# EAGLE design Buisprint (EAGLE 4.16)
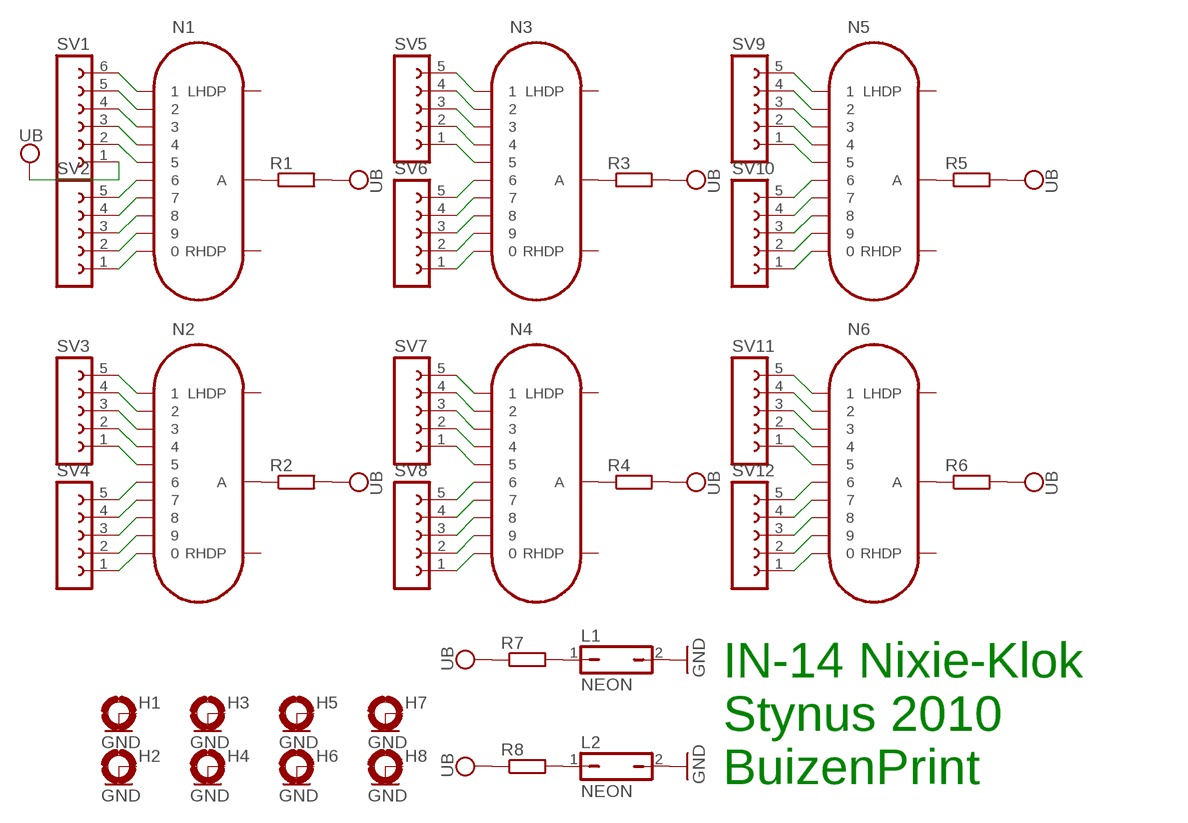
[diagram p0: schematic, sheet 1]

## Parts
H1  MOUNT-PAD-ROUND3.0  [3,0-PAD]
H2  MOUNT-PAD-ROUND3.0  [3,0-PAD]
H3  MOUNT-PAD-ROUND3.0  [3,0-PAD]
H4  MOUNT-PAD-ROUND3.0  [3,0-PAD]
H5  MOUNT-PAD-ROUND3.0  [3,0-PAD]
H6  MOUNT-PAD-ROUND3.0  [3,0-PAD]
H7  MOUNT-PAD-ROUND3.0  [3,0-PAD]
H8  MOUNT-PAD-ROUND3.0  [3,0-PAD]
L1  NEON  JP1Q  [JP1]
L2  NEON  JP1Q  [JP1]
N1  IN-14  [IN-14]
N2  IN-14  [IN-14]
N3  IN-14  [IN-14]
N4  IN-14  [IN-14]
N5  IN-14  [IN-14]
N6  IN-14  [IN-14]
R1  R-EU_0207/10  [0207/10]
R2  R-EU_0207/10  [0207/10]
R3  R-EU_0207/10  [0207/10]
R4  R-EU_0207/10  [0207/10]
R5  R-EU_0207/10  [0207/10]
R6  R-EU_0207/10  [0207/10]
R7  R-EU_0207/10  [0207/10]
R8  R-EU_0207/10  [0207/10]
SV1  FE06-1  [FE06]
SV2  FE05-1  [FE05-1]
SV3  FE05-1  [FE05-1]
SV4  FE05-1  [FE05-1]
SV5  FE05-1  [FE05-1]
SV6  FE05-1  [FE05-1]
SV7  FE05-1  [FE05-1]
SV8  FE05-1  [FE05-1]
SV9  FE05-1  [FE05-1]
SV10  FE05-1  [FE05-1]
SV11  FE05-1  [FE05-1]
SV12  FE05-1  [FE05-1]

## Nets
GND: H1.B3,0(MOUNT) H2.B3,0(MOUNT) H3.B3,0(MOUNT) H4.B3,0(MOUNT) H5.B3,0(MOUNT) H6.B3,0(MOUNT) H7.B3,0(MOUNT) H8.B3,0(MOUNT) L1.2 L2.2
N$1: N1.5 SV1.2
N$2: N1.4 SV1.3
N$3: N1.3 SV1.4
N$4: N1.2 SV1.5
N$5: N1.1 SV1.6
N$6: N1.0 SV2.1
N$7: N1.9 SV2.2
N$8: N1.8 SV2.3
N$9: N1.7 SV2.4
N$10: N1.6 SV2.5
N$11: N2.5 SV3.1
N$12: N2.4 SV3.2
N$13: N2.3 SV3.3
N$14: N2.2 SV3.4
N$15: N2.1 SV3.5
N$16: N2.0 SV4.1
N$17: N2.9 SV4.2
N$18: N2.8 SV4.3
N$19: N2.7 SV4.4
N$20: N2.6 SV4.5
N$21: N3.5 SV5.1
N$22: N3.4 SV5.2
N$23: N3.3 SV5.3
N$24: N3.2 SV5.4
N$25: N3.1 SV5.5
N$26: N3.0 SV6.1
N$27: N3.9 SV6.2
N$28: N3.8 SV6.3
N$29: N3.7 SV6.4
N$30: N3.6 SV6.5
N$31: N4.5 SV7.1
N$32: N4.4 SV7.2
N$33: N4.3 SV7.3
N$34: N4.2 SV7.4
N$35: N4.1 SV7.5
N$36: N4.0 SV8.1
N$37: N4.9 SV8.2
N$38: N4.8 SV8.3
N$39: N4.7 SV8.4
N$40: N4.6 SV8.5
N$41: N5.5 SV9.1
N$42: N5.4 SV9.2
N$43: N5.3 SV9.3
N$44: N5.2 SV9.4
N$45: N5.1 SV9.5
N$46: N5.0 SV10.1
N$47: N5.9 SV10.2
N$48: N5.8 SV10.3
N$49: N5.7 SV10.4
N$50: N5.6 SV10.5
N$51: N6.5 SV11.1
N$52: N6.4 SV11.2
N$53: N6.3 SV11.3
N$54: N6.2 SV11.4
N$55: N6.1 SV11.5
N$56: N6.0 SV12.1
N$57: N6.9 SV12.2
N$58: N6.8 SV12.3
N$59: N6.7 SV12.4
N$60: N6.6 SV12.5
N$61: N1.A R1.1
N$62: N2.A R2.1
N$63: N3.A R3.1
N$64: N4.A R4.1
N$65: N5.A R5.1
N$66: N6.A R6.1
N$67: L1.1 R7.2
N$68: L2.1 R8.2
VSS: R1.2 R2.2 R3.2 R4.2 R5.2 R6.2 R7.1 R8.1 SV1.1 ; supply symbol labelled UB
Unconnected: N1.LHDP N1.RHDP N2.LHDP N2.RHDP N3.LHDP N3.RHDP N4.LHDP N4.RHDP N5.LHDP N5.RHDP N6.LHDP N6.RHDP

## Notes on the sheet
- IN-14 Nixie-Klok
- Stynus 2010
- BuizenPrint

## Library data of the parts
H1-H8 = holes:MOUNT-PAD-ROUND: MOUNTING PAD, round
L1 L2 = jumper:JP1Q: JUMPER
N1-N6 = russian-nixies:IN-14: IN-14: medium numeric frontview nixie tube
R1-R8 = rcl:R-EU_: RESISTOR, European symbol
SV1 = con-lsta:FE06-1: FEMALE HEADER
SV2-SV12 = con-lsta:FE05-1: FEMALE HEADER

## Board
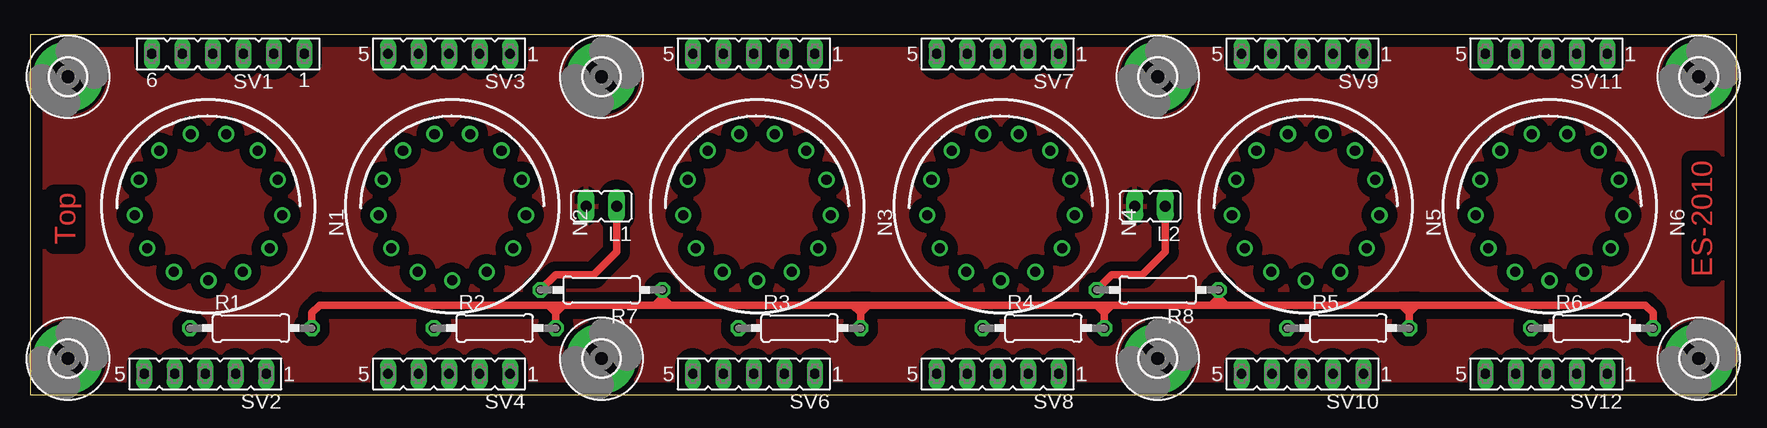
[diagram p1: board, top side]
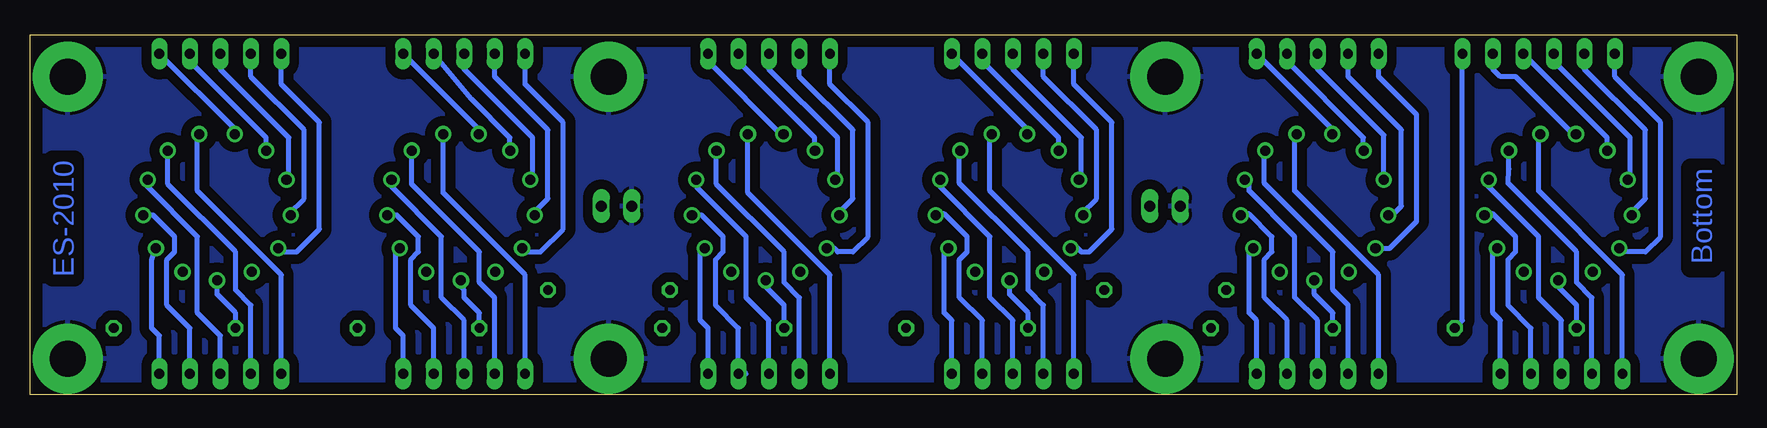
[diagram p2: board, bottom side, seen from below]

Size 142.22 x 30 mm. Coordinates in mm from the lower left corner, seen from the top.
Outline: 0,0 142.22,0 142.22,30 0,30 0,0
Copper layers (1*16): Top 0.035mm / dielectric 1.5mm / Bottom 0.035mm
Design rules "default": minimum track width 10mil, minimum drill 24mil, track to track 8mil, track to pad 8mil, pad to pad 8mil, via to via 8mil, smd to smd 8mil, copper to edge 40mil, drill to drill 8mil, minimum pad ring 10mil, minimum via ring 8mil, stop-mask expansion 4mil, vias tented up to drill 0mil, thermal gap 10mil

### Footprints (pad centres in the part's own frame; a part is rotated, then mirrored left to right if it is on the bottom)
3,0-PAD = drill 3 pad 5.842 round: B3,0 0,0
JP1 = drill 0.914 long: 1 0,-1.27; 2 0,1.27
IN-14 = drill 0.84 round: 0 5.094,-3.516; 1 -5.094,-3.516; 2 -6.145,-0.746; 3 -5.788,2.195; 4 -4.105,4.633; 5 -1.481,6.01; 6 1.481,6.01; 7 4.105,4.633; 8 5.788,2.195; 9 6.145,-0.746; A 0,-6.19; LHDP 2.877,-5.481; RHDP -2.877,-5.481
0207/10 = drill 0.813 octagon: 1 -5.08,0; 2 5.08,0
FE06 = drill 0.813 long: 1 -6.35,0; 2 -3.81,0; 3 -1.27,0; 4 1.27,0; 5 3.81,0; 6 6.35,0
FE05-1 = drill 0.813 long: 1 -5.08,0; 2 -2.54,0; 3 0,0; 4 2.54,0; 5 5.08,0

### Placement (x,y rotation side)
H1  3.17,26.5 0 top
H2  3.17,3.01 0 top
H3  47.62,26.5 0 top
H4  47.62,3.01 0 top
H5  93.97,26.5 0 top
H6  93.97,3.01 0 top
H7  139.06,26.5 0 top
H8  139.06,3.01 0 top
L1  47.62,15.71 90 top
L2  93.34,15.71 90 top
N1  14.87,15.71 0 top
N2  35.19,15.71 0 top
N3  60.59,15.71 0 top
N4  80.91,15.71 0 top
N5  106.31,15.71 0 top
N6  126.63,15.71 0 top
R1  18.41,5.55 0 top
R2  38.73,5.55 0 top
R3  64.13,5.55 0 top
R4  84.45,5.55 0 top
R5  109.85,5.55 0 top
R6  130.17,5.55 0 top
R7  47.62,8.73 180 top
R8  93.97,8.73 180 top
SV1  16.5,28.41 180 top
SV2  14.6,1.74 180 top
SV3  34.92,28.41 180 top
SV4  34.92,1.74 180 top
SV5  60.32,28.41 180 top
SV6  60.32,1.74 180 top
SV7  80.64,28.41 180 top
SV8  80.64,1.74 180 top
SV9  106.04,28.41 180 top
SV10  106.04,1.74 180 top
SV11  126.36,28.41 180 top
SV12  126.36,1.74 180 top

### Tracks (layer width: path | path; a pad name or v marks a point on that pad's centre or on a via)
GND
  pour Bottom (isolate 0.813): -0.01,30.31 142.23,30.31 142.23,-0.17 -0.01,-0.17
  pour Top (isolate 0.813): -0.01,30.31 142.23,30.31 142.23,-0.17 -0.01,-0.17
N$1
  Bottom 0.406: 13.33,22.06 13.39,22 N1.5 13.62,21.72 18.41,26.5 19.68,26.5 20.31,27.14 SV1.2
N$2
  Bottom 0.406: N1.4 10.77,20.77 10.79,20.79 10.79,21.42 SV1.3
N$3
  Bottom 0.406: 8.89,18.25 8.89,21.42 15.24,27.77 SV1.4 | 8.89,18.25 9.08,18.05 N1.3 | 8.89,18.25 9.52,17.61
N$4
  Bottom 0.406: N1.2 8.77,14.96 8.89,15.08 7.62,16.34 7.62,22.06 12.7,27.14 SV1.5
N$5
  Bottom 0.406: N1.1 9.78,12.16 9.52,11.9 7.62,11.9 6.34,13.17 6.34,22.7 10.16,26.5 SV1.6
N$6
  Bottom 0.406: SV2.1 19.68,6.18 20.31,6.82 20.31,11.9 19.97,12.19 N1.0
N$7
  Bottom 0.406: SV2.2 17.14,5.55 19.04,7.46 19.04,11.27 18.41,11.9 18.41,13.17 20.31,15.08 20.95,15.08 21.02,15.01 N1.9
N$8
  Bottom 0.406: SV2.3 14.6,6.18 16.5,8.09 16.5,13.17 20.95,17.61 20.66,17.96 | 20.66,17.96 20.95,18.25 | 20.66,17.96 N1.8
N$9
  Bottom 0.406: N1.7 18.97,18.81 19.04,17.61 13.33,11.9 13.33,9.36 12.06,8.09 SV2.4
N$10
  Bottom 0.406: SV2.5 9.52,10 16.5,16.98 16.5,22.06 16.35,21.91 N1.6
N$11
  Bottom 0.406: N2.5 33.71,22.12 SV3.1
N$12
  Bottom 0.406: SV3.2 37.46,27.77 31.11,21.42 31.11,20.15 31.08,20.18 N2.4
N$13
  Bottom 0.406: N2.3 29.4,21.62 34.92,27.14 SV3.3
N$14
  Bottom 0.406: SV3.4 32.38,26.5 27.93,22.06 27.93,15.71 28.68,14.96 N2.2
N$15
  Bottom 0.406: N2.1 28.91,12.19 26.66,14.44 26.66,23.33 29.84,26.5 SV3.5
N$16
  Bottom 0.406: SV4.1 40,6.18 40.64,6.82 40.64,11.9 40.34,12.19 N2.0
N$17
  Bottom 0.406: SV4.2 37.46,6.18 39.37,8.09 39.37,11.27 38.73,11.9 38.73,13.17 40.64,15.08 41.27,15.08 41.34,15.01 N2.9
N$18
  Bottom 0.406: SV4.3 34.92,6.18 36.83,8.09 36.83,13.17 40.64,16.98 40.64,17.61 40.93,17.9 N2.8
N$19
  Bottom 0.406: SV4.4 32.38,7.46 33.65,8.73 33.65,11.9 39.37,17.61 39.37,20.15 39.3,20.22 N2.7
N$20
  Bottom 0.406: SV4.5 29.84,10 36.83,16.98 36.83,21.42 36.67,21.58 N2.6
N$21
  Bottom 0.406: N3.5 59.11,22.12 SV5.1
N$22
  Bottom 0.406: SV5.2 62.86,27.77 56.51,21.42 56.51,20.15 56.48,20.18 N3.4
N$23
  Bottom 0.406: SV5.3 60.32,27.14 54.61,21.42 54.61,17.61 54.8,17.81 N3.3
N$24
  Bottom 0.406: SV5.4 57.78,26.5 53.34,22.06 53.34,16.34 54.61,15.08 54.49,14.96 N3.2
N$25
  Bottom 0.406: SV5.5 55.24,25.87 52.07,22.7 52.07,13.81 53.97,11.9 54.61,11.9 55.24,12.54 55.5,12.28 N3.1
N$26
  Bottom 0.406: N3.0 65.68,12.25 66.03,11.9 66.03,6.82 65.4,6.18 SV6.1
N$27
  Bottom 0.406: SV6.2 62.86,6.18 64.77,8.09 64.77,11.27 64.13,11.9 64.13,13.17 66.03,15.08 66.67,15.08 66.73,15.01 N3.9
N$28
  Bottom 0.406: SV6.3 60.32,6.18 62.23,8.09 62.23,13.17 66.32,17.27 N3.8
N$29
  Bottom 0.406: SV6.4 57.78,7.46 59.05,8.73 59.05,11.9 64.77,17.61 64.77,20.15 64.69,20.22 N3.7
N$30
  Bottom 0.406: SV6.5 55.24,10 62.23,16.98 62.23,22.06 62.07,21.91 N3.6
N$31
  Bottom 0.406: SV7.1 85.72,27.77 79.43,21.48 | 79.43,21.48 79.37,21.42 | N4.5 79.43,21.48
N$32
  Bottom 0.406: SV7.2 83.18,27.77 76.83,21.42 76.83,20.15 76.8,20.18 N4.4
N$33
  Bottom 0.406: SV7.3 80.64,27.14 74.92,21.42 74.92,17.61 75.12,17.81 N4.3
N$34
  Bottom 0.406: SV7.4 78.1,26.5 73.66,22.06 73.66,16.34 74.92,15.08 74.81,14.96 N4.2
N$35
  Bottom 0.406: SV7.5 75.56,25.87 72.38,22.7 72.38,13.17 73.66,11.9 74.92,11.9 75.56,12.54 75.82,12.28 N4.1
N$36
  Bottom 0.406: SV8.1 85.72,5.55 86.35,6.18 86.35,11.9 N4.0
N$37
  Bottom 0.406: N4.9 86.24,14.96 84.45,13.17 84.45,11.9 85.08,11.27 85.08,7.46 83.18,5.55 83.18,2.38 82.55,1.74 SV8.2
N$38
  Bottom 0.406: N4.8 86.64,17.27 82.55,13.17 82.55,8.09 80.64,6.18 SV8.3
N$39
  Bottom 0.406: N4.7 85.02,17.54 79.37,11.9 79.37,9.36 78.1,8.09 SV8.4
N$40
  Bottom 0.406: N4.6 82.39,16.83 75.56,10 SV8.5
N$41
  Bottom 0.406: N5.5 104.83,22.12 SV9.1
N$42
  Bottom 0.406: SV9.2 105.41,24.6 102.23,21.42 102.23,20.79 102.2,20.77 N5.4
N$43
  Bottom 0.406: SV9.3 106.04,27.14 100.32,21.42 100.32,17.61 100.52,17.81 N5.3
N$44
  Bottom 0.406: SV9.4 103.5,26.5 99.05,22.06 99.05,16.34 100.32,15.08 100.21,14.96 N5.2
N$45
  Bottom 0.406: SV9.5 100.96,25.87 97.78,22.7 97.78,13.81 99.69,11.9 100.96,11.9 101.22,12.16 N5.1
N$46
  Bottom 0.406: SV10.1 111.12,4.92 111.75,5.55 111.75,11.9 N5.0
N$47
  Bottom 0.406: N5.9 111.64,14.96 109.85,13.17 109.85,11.9 110.48,11.27 110.48,7.46 108.58,5.55 SV10.2
N$48
  Bottom 0.406: N5.8 112.05,17.27 107.94,13.17 107.94,8.09 106.04,6.18 SV10.3
N$49
  Bottom 0.406: N5.7 110.41,17.54 104.77,11.9 104.77,9.36 103.5,8.09 SV10.4
N$50
  Bottom 0.406: N5.6 107.79,16.83 100.96,10 SV10.5
N$51
  Bottom 0.406: SV11.1 125.09,22.06 125.15,22 N6.5
N$52
  Bottom 0.406: SV11.2 128.9,27.77 122.55,21.42 122.55,20.15 122.52,20.18 N6.4
N$53
  Bottom 0.406: SV11.3 126.36,27.14 120.64,21.42 120.64,17.61 120.84,17.81 N6.3
N$54
  Bottom 0.406: SV11.4 123.82,26.5 119.38,22.06 119.38,16.34 120.64,15.08 120.53,14.96 N6.2
N$55
  Bottom 0.406: SV11.5 121.28,25.87 118.1,22.7 118.1,13.81 120.01,11.9 121.28,11.9 121.54,12.16 N6.1
N$56
  Bottom 0.406: SV12.1 131.44,4.92 132.07,5.55 132.07,11.27 N6.0
N$57
  Bottom 0.406: N6.9 131.96,14.96 130.17,13.17 130.17,11.9 130.81,11.27 130.81,7.46 128.9,5.55 SV12.2
N$58
  Bottom 0.406: N6.8 132.42,17.32 128.27,13.17 128.27,6.82 126.36,4.92 SV12.3
N$59
  Bottom 0.406: N6.7 130.73,17.54 125.09,11.9 125.09,8.73 123.82,7.46 SV12.4
N$60
  Bottom 0.406: SV12.5 121.28,10 128.27,16.98 128.27,21.42 128.11,21.58 N6.6
N$61
  Bottom 0.406: N1.A 14.87,9 13.33,7.46 R1.1
N$62
  Bottom 0.406: N2.A 35.19,8.36 33.65,6.82 R2.1
N$63
  Bottom 0.406: N3.A 60.59,8.36 59.05,6.82 R3.1
N$64
  Bottom 0.406: N4.A 80.91,9 79.37,7.46 R4.1
N$65
  Bottom 0.406: R5.1 104.77,6.82 106.04,8.09 106.04,8.73 106.67,9.36 106.52,9.52 N5.A
N$66
  Bottom 0.406: N6.A 126.63,8.36 125.09,6.82 R6.1
N$67
  Top 0.61: L1.1 48.89,11.9 46.98,10 43.81,10 R7.2
N$68
  Top 0.61: R8.2 90.16,10 92.7,10 94.61,11.9 L2.1
VSS
  Top 0.61: 43.18,7.46 24.12,7.46 23.49,6.82 R1.2 | 43.18,7.46 43.81,7.46 | 43.81,7.46 44.45,7.46 | 68.57,7.46 69.21,7.46 | 69.21,7.46 69.84,7.46 | 69.84,7.46 88.89,7.46 | 88.89,7.46 89.53,7.46 | 89.53,7.46 90.16,7.46 | 99.05,7.46 99.69,7.46 | 99.69,7.46 114.3,7.46 | 114.3,7.46 114.93,7.46 | 114.93,7.46 115.56,7.46 | 115.56,7.46 134.62,7.46 135.25,6.82 R6.2 | 114.93,7.46 114.93,6.82 | 114.93,6.82 R5.2 | 89.53,7.46 89.53,6.82 | 89.53,6.82 R4.2 | 69.21,7.46 69.21,6.82 | 69.21,6.82 R3.2 | 43.81,7.46 43.81,6.82 | 43.81,6.82 R2.2 | 44.45,7.46 43.81,6.82 | 43.18,7.46 44.45,7.46 | 43.18,7.46 43.81,6.82 | 69.84,7.46 69.21,6.82 | 68.57,7.46 69.84,7.46 | 68.57,7.46 69.21,6.82 | 89.53,6.82 90.16,7.46 | 88.89,7.46 89.53,6.82 | 114.3,7.46 114.93,6.82 | 114.93,6.82 115.56,7.46 | 44.45,7.46 52.07,7.46 | 52.07,7.46 52.7,7.46 | 53.34,7.46 68.57,7.46 | 90.16,7.46 98.42,7.46 | 98.42,7.46 99.05,7.46 | 99.05,7.46 99.05,8.09 | 99.05,8.09 R8.1 | 98.42,7.46 99.05,8.09 | 98.42,7.46 99.69,7.46 | 99.05,8.09 99.69,7.46 | 52.07,7.46 52.7,8.09 | 52.7,8.09 53.34,7.46 | 52.7,7.46 53.34,7.46 | 52.7,7.46 52.7,8.09 | 52.7,8.09 R7.1
  Bottom 0.406: SV1.1 22.86,6.18 R1.2

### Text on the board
Top: ES-2010 | Top
Bottom: ES-2010 | Bottom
